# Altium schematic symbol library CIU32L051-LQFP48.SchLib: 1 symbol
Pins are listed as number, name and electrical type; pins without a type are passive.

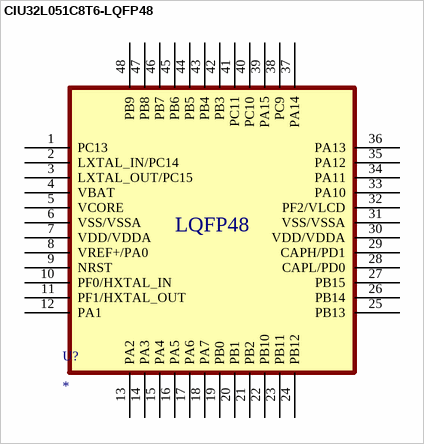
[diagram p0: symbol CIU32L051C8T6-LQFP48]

## CIU32L051C8T6-LQFP48
designator U?
footprint CIU32L051-LQFP_48N
pins: 1 PC13, 2 LXTAL_IN/PC14, 3 LXTAL_OUT/PC15, 4 VBAT, 5 VCORE, 6 VSS/VSSA, 7 VDD/VDDA, 8 VREF+/PA0, 9 NRST, 10 PF0/HXTAL_IN, 11 PF1/HXTAL_OUT, 12 PA1, 13 PA2, 14 PA3, 15 PA4, 16 PA5, 17 PA6, 18 PA7, 19 PB0, 20 PB1, 21 PB2, 22 PB10, 23 PB11, 24 PB12, 25 PB13, 26 PB14, 27 PB15, 28 CAPL/PD0, 29 CAPH/PD1, 30 VDD/VDDA, 31 VSS/VSSA, 32 PF2/VLCD, 33 PA10, 34 PA11, 35 PA12, 36 PA13, 37 PA14, 38 PC9, 39 PA15, 40 PC10, 41 PC11, 42 PB3, 43 PB4, 44 PB5, 45 PB6, 46 PB7, 47 PB8, 48 PB9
